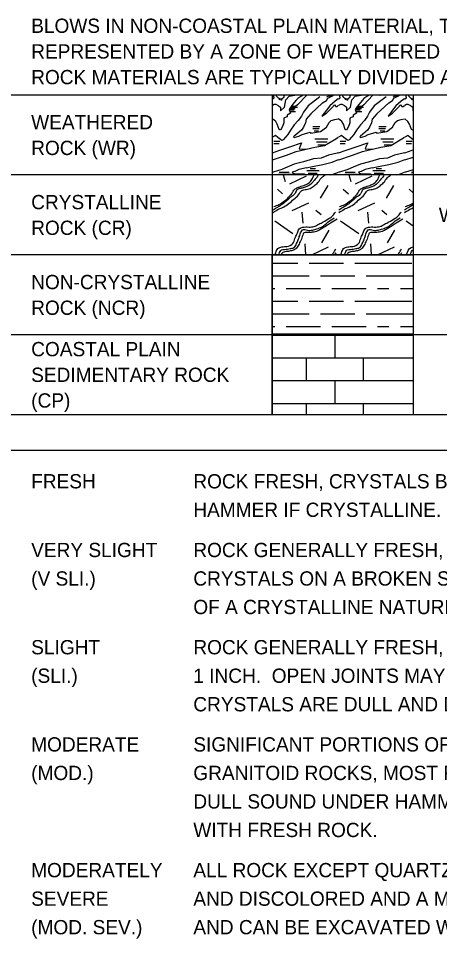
# Model space of a CAD drawing. Extents: x 265553 to 275568, y 168312 to 173522.
# Drawn here: x 267674.3 to 267802.5, y 170735.6 to 171015.3 of the extents above; entities that cross this region are included whole.
import ezdxf

# ---------------------------------------------------------------- set-up
doc = ezdxf.new("R2010")
doc.units = 0
doc.layers.add('Geotech Sheets and Borders Cell', color=7, linetype='Continuous')

msp = doc.modelspace()

# ---------------------------------------------------------------- linework, layer by layer
at = {"layer": 'Geotech Sheets and Borders Cell'}
for p, q in [((268066.96, 170992), (267670.42, 170992)), ((267751.59, 170992), (267751.59, 170894.83)), ((267757.4, 170991.93), (267757.43, 170992)), ((267760.6, 170991.93), (267760.68, 170992)), ((267764.2, 170991.93), (267764.29, 170992)), ((267777.52, 170991.93), (267777.55, 170992)), ((267780.72, 170991.93), (267780.8, 170992)), ((267784.32, 170991.93), (267784.41, 170992)), ((267794.45, 170992), (267794.45, 170894.83)), ((267756.74, 170987.47), (267758.22, 170987.47)), ((267756.87, 170987.91), (267758.59, 170987.91)), ((267757.12, 170988.29), (267759.26, 170988.29)), ((267776.86, 170987.47), (267778.34, 170987.47)), ((267776.99, 170987.91), (267778.71, 170987.91)), ((267777.24, 170988.29), (267779.38, 170988.29)), ((267756.88, 170986.98), (267758.68, 170986.98)), ((267777, 170986.98), (267778.8, 170986.98)), ((267763.88, 170982.48), (267766.08, 170982.48)), ((267763.88, 170981.81), (267765.88, 170981.81)), ((267784, 170982.48), (267786.2, 170982.48)), ((267784, 170981.81), (267786, 170981.81)), ((267764.28, 170981.13), (267765.68, 170981.13)), ((267784.4, 170981.13), (267785.8, 170981.13)), ((267752.08, 170977.98), (267753.88, 170977.98)), ((267752.08, 170977.31), (267753.68, 170977.31)), ((267764.48, 170978.66), (267768.48, 170978.66)), ((267765.08, 170977.76), (267768.28, 170977.76)), ((267765.48, 170976.86), (267767.68, 170976.86)), ((267772.2, 170977.98), (267774, 170977.98)), ((267772.2, 170977.31), (267773.8, 170977.31)), ((267784.6, 170978.66), (267788.6, 170978.66)), ((267785.2, 170977.76), (267788.4, 170977.76)), ((267785.6, 170976.86), (267787.8, 170976.86)), ((267792.32, 170977.98), (267794.12, 170977.98)), ((267792.32, 170977.31), (267793.92, 170977.31)), ((267753.49, 170967.92), (267757.43, 170967.92)), ((267753.68, 170968.53), (267756.68, 170968.53)), ((267762.08, 170969.07), (267765.83, 170969.07)), ((267762.48, 170968.31), (267765.28, 170968.31)), ((267763.08, 170969.66), (267764.68, 170969.66)), ((267773.61, 170967.92), (267777.55, 170967.92)), ((267773.8, 170968.53), (267776.8, 170968.53)), ((267782.2, 170969.07), (267785.95, 170969.07)), ((267782.6, 170968.31), (267785.4, 170968.31)), ((267783.2, 170969.66), (267784.8, 170969.66)), ((267793.73, 170967.92), (267794.45, 170967.92)), ((267793.92, 170968.53), (267794.45, 170968.53)), ((268066.96, 170967.71), (267670.42, 170967.71)), ((267794.45, 170958.67), (267793.41, 170958.02)), ((268066.96, 170943.42), (267670.42, 170943.42)), ((267770.89, 170944.06), (267770.55, 170943.46)), ((267790.89, 170944.06), (267790.55, 170943.46)), ((267794.45, 170943.74), (267794.29, 170943.46)), ((267751.55, 170940.9), (267752.41, 170940.9)), ((267752.41, 170940.9), (267759.35, 170940.9)), ((267762.82, 170940.9), (267773.24, 170940.9)), ((267776.71, 170940.9), (267787.12, 170940.9)), ((267787.12, 170940.9), (267794.06, 170940.9)), ((267751.55, 170937.08), (267752.41, 170937.08)), ((267752.41, 170937.08), (267762.82, 170937.08)), ((267766.29, 170937.08), (267776.71, 170937.08)), ((267780.18, 170937.08), (267787.12, 170937.08)), ((267787.12, 170937.08), (267794.4, 170937.08)), ((267751.55, 170933.22), (267752.37, 170933.22)), ((267755.84, 170933.22), (267766.25, 170933.22)), ((267769.72, 170933.22), (267780.13, 170933.22)), ((267783.6, 170933.22), (267787.07, 170933.22)), ((267790.54, 170933.22), (267794.4, 170933.22)), ((267751.55, 170929.36), (267752.41, 170929.36)), ((267752.41, 170929.36), (267759.35, 170929.36)), ((267762.82, 170929.36), (267773.24, 170929.36)), ((267776.71, 170929.36), (267787.12, 170929.36)), ((267787.12, 170929.36), (267794.06, 170929.36)), ((267751.55, 170925.5), (267752.41, 170925.5)), ((267752.41, 170925.5), (267762.82, 170925.5)), ((267766.29, 170925.5), (267776.71, 170925.5)), ((267780.18, 170925.5), (267787.12, 170925.5)), ((267787.12, 170925.5), (267794.4, 170925.5)), ((267751.55, 170921.64), (267752.37, 170921.64)), ((267755.84, 170921.64), (267766.25, 170921.64)), ((267769.72, 170921.64), (267780.13, 170921.64)), ((267783.6, 170921.64), (267787.07, 170921.64)), ((267790.54, 170921.64), (267794.4, 170921.64)), ((268066.96, 170919.12), (267670.42, 170919.12)), ((267770.68, 170912.14), (267770.68, 170918.99)), ((267751.59, 170912.14), (267794.45, 170912.14)), ((267762, 170905.2), (267762, 170912.14)), ((267779.35, 170905.2), (267779.35, 170912.14)), ((267751.59, 170905.2), (267794.45, 170905.2)), ((267770.68, 170898.26), (267770.68, 170905.2)), ((267751.59, 170898.26), (267794.45, 170898.26)), ((267762, 170894.83), (267762, 170898.26)), ((267779.35, 170894.83), (267779.35, 170898.26)), ((268066.96, 170894.83), (267670.42, 170894.83)), ((268066.96, 170883.98), (267670.42, 170883.98))]:
    msp.add_line(p, q, dxfattribs=at)
for points in [[(267751.64, 170990.85), (267752.14, 170991.13), (267752.05, 170991.72), (267751.95, 170992)], [(267762.08, 170991.93), (267759.28, 170989.01), (267758.68, 170988.56), (267757.28, 170988.56), (267756.68, 170987.66), (267756.88, 170986.98), (267757.08, 170986.53), (267756.08, 170985.86), (267756.08, 170985.41), (267756.08, 170985.41), (267755.48, 170985.18), (267755.08, 170984.96), (267755.08, 170983.61), (267754.68, 170982.48), (267754.08, 170981.36), (267753.68, 170981.58), (267753.08, 170983.16), (267752.62, 170984.01)], [(267753.28, 170991.26), (267752.88, 170991.71), (267752.88, 170992)], [(267753.28, 170991.26), (267753.48, 170991.03), (267753.88, 170990.58), (267754.08, 170991.03), (267754.28, 170990.58), (267754.48, 170990.58), (267754.68, 170991.03), (267755.08, 170991.26), (267755.28, 170991.93)], [(267766.08, 170991.48), (267762.48, 170988.78), (267761.08, 170986.76), (267760.48, 170985.63), (267759.48, 170984.28), (267758.28, 170982.93), (267757.08, 170981.36), (267756.28, 170980.01), (267754.88, 170978.43), (267754.48, 170978.21), (267753.28, 170979.11)], [(267753.51, 170988.73), (267754.08, 170988.33), (267754.08, 170987.21), (267755.28, 170988.33), (267755.68, 170990.58), (267756.68, 170991.71), (267758.48, 170991.93)], [(267760.91, 170992), (267760.63, 170991.74), (267760.25, 170991.55), (267759.35, 170990.98), (267758.76, 170990.37), (267757.85, 170989.27), (267757.28, 170988.56)], [(267771.64, 170990.85), (267770.68, 170990.13), (267769.08, 170988.78), (267768.08, 170987.43), (267766.68, 170985.63), (267768.08, 170986.53), (267769.68, 170988.11), (267770.48, 170989.01), (267770.88, 170988.56), (267771.28, 170988.56), (267771.64, 170988.88)], [(267766.88, 170989.68), (267768.08, 170990.36), (267768.48, 170991.03), (267769.68, 170991.71), (267770.08, 170991.93)], [(267768.2, 170991.48), (267768.58, 170991.63), (267769.14, 170991.75), (267769.83, 170991.97), (267769.87, 170992)], [(267771.76, 170990.85), (267772.26, 170991.13), (267772.17, 170991.72), (267772.07, 170992)], [(267772.2, 170991.93), (267772.34, 170992)], [(267782.2, 170991.93), (267779.4, 170989.01), (267778.8, 170988.56), (267777.4, 170988.56), (267776.8, 170987.66), (267777, 170986.98), (267777.2, 170986.53), (267776.2, 170985.86), (267776.2, 170985.41), (267776.2, 170985.41), (267775.6, 170985.18), (267775.2, 170984.96), (267775.2, 170983.61), (267774.8, 170982.48), (267774.2, 170981.36), (267773.8, 170981.58), (267773.2, 170983.16), (267772.74, 170984.01)], [(267773.4, 170991.26), (267773, 170991.71), (267773, 170992)], [(267773.4, 170991.26), (267773.6, 170991.03), (267774, 170990.58), (267774.2, 170991.03), (267774.4, 170990.58), (267774.6, 170990.58), (267774.8, 170991.03), (267775.2, 170991.26), (267775.4, 170991.93)], [(267786.2, 170991.48), (267782.6, 170988.78), (267781.2, 170986.76), (267780.6, 170985.63), (267779.6, 170984.28), (267778.4, 170982.93), (267777.2, 170981.36), (267776.4, 170980.01), (267775, 170978.43), (267774.6, 170978.21), (267773.4, 170979.11)], [(267773.63, 170988.73), (267774.2, 170988.33), (267774.2, 170987.21), (267775.4, 170988.33), (267775.8, 170990.58), (267776.8, 170991.71), (267778.6, 170991.93)], [(267781.03, 170992), (267780.75, 170991.74), (267780.37, 170991.55), (267779.47, 170990.98), (267778.88, 170990.37), (267777.97, 170989.27), (267777.4, 170988.56)], [(267791.76, 170990.85), (267790.8, 170990.13), (267789.2, 170988.78), (267788.2, 170987.43), (267786.8, 170985.63), (267788.2, 170986.53), (267789.8, 170988.11), (267790.6, 170989.01), (267791, 170988.56), (267791.4, 170988.56), (267791.76, 170988.88)], [(267787, 170989.68), (267788.2, 170990.36), (267788.6, 170991.03), (267789.8, 170991.71), (267790.2, 170991.93)], [(267788.32, 170991.48), (267788.7, 170991.63), (267789.26, 170991.75), (267789.95, 170991.97), (267789.99, 170992)], [(267791.88, 170990.85), (267792.38, 170991.13), (267792.29, 170991.72), (267792.19, 170992)], [(267792.32, 170991.93), (267792.46, 170992)], [(267793.52, 170991.26), (267793.12, 170991.71), (267793.12, 170992)], [(267793.52, 170991.26), (267793.72, 170991.03), (267794.12, 170990.58), (267794.32, 170991.03), (267794.45, 170990.73)], [(267753.51, 170988.73), (267752.73, 170989.12), (267752.19, 170989.12), (267751.64, 170988.88)], [(267766.88, 170989.68), (267763.28, 170986.31), (267761.88, 170984.73), (267761.68, 170983.61), (267761.08, 170982.26), (267760.48, 170981.36), (267758.28, 170979.56), (267758.08, 170979.33), (267758.28, 170979.11), (267759.68, 170979.56), (267760.68, 170980.01), (267763.08, 170980.68), (267763.28, 170980.46), (267766.28, 170980.91), (267768.08, 170982.26), (267768.86, 170983.66)], [(267773.63, 170988.73), (267772.85, 170989.12), (267772.31, 170989.12), (267771.76, 170988.88)], [(267787, 170989.68), (267783.4, 170986.31), (267782, 170984.73), (267781.8, 170983.61), (267781.2, 170982.26), (267780.6, 170981.36), (267778.4, 170979.56), (267778.2, 170979.33), (267778.4, 170979.11), (267779.8, 170979.56), (267780.8, 170980.01), (267783.2, 170980.68), (267783.4, 170980.46), (267786.4, 170980.91), (267788.2, 170982.26), (267788.98, 170983.66)], [(267793.75, 170988.73), (267792.97, 170989.12), (267792.43, 170989.12), (267791.88, 170988.88)], [(267793.75, 170988.73), (267794.32, 170988.33), (267794.32, 170987.21), (267794.45, 170987.33)], [(267752.62, 170984.01), (267751.63, 170984.81)], [(267768.86, 170983.66), (267769.52, 170984.32), (267770.65, 170984.62), (267771.63, 170984.81)], [(267772.74, 170984.01), (267771.75, 170984.81)], [(267788.98, 170983.66), (267789.64, 170984.32), (267790.77, 170984.62), (267791.75, 170984.81)], [(267792.86, 170984.01), (267791.87, 170984.81)], [(267794.45, 170981.6), (267794.32, 170981.36), (267793.92, 170981.58), (267793.32, 170983.16), (267792.86, 170984.01)], [(267753.28, 170979.11), (267752.54, 170979.67), (267751.64, 170979.21)], [(267751.68, 170972.36), (267755.88, 170973.71), (267758.88, 170974.83), (267764.48, 170976.18), (267767.48, 170976.63), (267770.88, 170978.66), (267771.64, 170979.21)], [(267773.4, 170979.11), (267772.66, 170979.67), (267771.76, 170979.21)], [(267771.8, 170972.36), (267776, 170973.71), (267779, 170974.83), (267784.6, 170976.18), (267787.6, 170976.63), (267791, 170978.66), (267791.76, 170979.21)], [(267793.52, 170979.11), (267792.78, 170979.67), (267791.88, 170979.21)], [(267794.45, 170978.41), (267793.52, 170979.11)], [(267751.64, 170974.47), (267753.91, 170975.26), (267756.94, 170976.24), (267760.51, 170977.47), (267760.07, 170976.49), (267759.73, 170975.65), (267761.93, 170975.61)], [(267771.76, 170974.47), (267774.03, 170975.26), (267777.06, 170976.24), (267780.63, 170977.47), (267780.19, 170976.49), (267779.85, 170975.65), (267782.05, 170975.61)], [(267771.64, 170974.47), (267771.28, 170974.38), (267768.68, 170973.71), (267766.48, 170972.81), (267764.08, 170972.58), (267761.08, 170971.68), (267758.28, 170971.01), (267756.08, 170970.11), (267754.48, 170969.43), (267751.88, 170968.53), (267751.68, 170968.53)], [(267791.76, 170974.47), (267791.4, 170974.38), (267788.8, 170973.71), (267786.6, 170972.81), (267784.2, 170972.58), (267781.2, 170971.68), (267778.4, 170971.01), (267776.2, 170970.11), (267774.6, 170969.43), (267772, 170968.53), (267771.8, 170968.53)], [(267791.88, 170974.47), (267794.15, 170975.26), (267794.45, 170975.35)], [(267751.59, 170972.38), (267751.63, 170972.4)], [(267761.86, 170969.88), (267763.77, 170970.29), (267766.96, 170970.88), (267769.8, 170971.61), (267771.75, 170972.4)], [(267781.98, 170969.88), (267783.89, 170970.29), (267787.08, 170970.88), (267789.92, 170971.61), (267791.87, 170972.4)], [(267791.92, 170972.36), (267794.45, 170973.17)], [(267761.86, 170969.88), (267761.08, 170969.66), (267759.68, 170969.43), (267758.48, 170968.76), (267757.68, 170968.53), (267757.88, 170968.31), (267758.88, 170968.08), (267760.68, 170968.08), (267761.28, 170968.08), (267761.44, 170967.71)], [(267769.35, 170967.71), (267770.14, 170967.94), (267771.68, 170968.53)], [(267781.98, 170969.88), (267781.2, 170969.66), (267779.8, 170969.43), (267778.6, 170968.76), (267777.8, 170968.53), (267778, 170968.31), (267779, 170968.08), (267780.8, 170968.08), (267781.4, 170968.08), (267781.56, 170967.71)], [(267789.47, 170967.71), (267790.26, 170967.94), (267791.8, 170968.53)], [(267794.45, 170969.33), (267792.12, 170968.53), (267791.92, 170968.53)], [(267754.86, 170967.71), (267755.49, 170965.74)], [(267756.88, 170965.07), (267761.96, 170967.43)], [(267774.86, 170967.71), (267775.49, 170965.74)], [(267776.88, 170965.07), (267781.96, 170967.43)], [(267753.18, 170963.39), (267754.74, 170962.03)], [(267768.46, 170964.53), (267766.18, 170960.65)], [(267773.18, 170963.39), (267774.74, 170962.03)], [(267788.46, 170964.53), (267786.18, 170960.65)], [(267793.18, 170963.39), (267794.45, 170962.28)], [(267757.66, 170956.91), (267762.74, 170959.27)], [(267764.88, 170957.06), (267766.44, 170955.7)], [(267777.66, 170956.91), (267782.74, 170959.27)], [(267784.88, 170957.06), (267786.44, 170955.7)], [(267760.6, 170956.39), (267760.84, 170953.07)], [(267780.6, 170956.39), (267780.84, 170953.07)], [(267752.31, 170953.74), (267757.87, 170949.9)], [(267768.8, 170950.99), (267766.52, 170947.11)], [(267772.31, 170953.74), (267777.87, 170949.9)], [(267788.8, 170950.99), (267786.52, 170947.11)], [(267792.31, 170953.74), (267794.45, 170952.26)], [(267761.47, 170946.76), (267761.71, 170943.46)], [(267763.64, 170943.47), (267768.72, 170945.83)], [(267781.47, 170946.76), (267781.71, 170943.46)], [(267783.64, 170943.47), (267788.72, 170945.83)]]:
    msp.add_lwpolyline(points, dxfattribs=at)
for points in [[(267751.55, 170943.46), (267794.4, 170943.46), (267794.4, 170919.3), (267751.55, 170919.3)], [(267751.59, 170918.99), (267794.45, 170918.99), (267794.45, 170894.83), (267751.59, 170894.83)]]:
    msp.add_lwpolyline(points, close=True, dxfattribs=at)
for points in [[(267752.01, 170958.18), (267753.61, 170958.7), (267755.29, 170959.86), (267756.53, 170960.94), (267756.77, 170961.3), (267757.57, 170962.14), (267758.09, 170963.06), (267759.09, 170963.78), (267760.01, 170964.14), (267761.61, 170964.7), (267762.57, 170965.18), (267763.65, 170966.38), (267764.13, 170967.38), (267764.35, 170967.71)], [(267765.52, 170967.71), (267765.21, 170967.1), (267764.41, 170966.18), (267763.69, 170965.3), (267762.57, 170964.46), (267761.57, 170964.02), (267760.37, 170963.66), (267759.69, 170963.5), (267758.93, 170963.02), (267758.69, 170962.54), (267758.25, 170961.78), (267757.01, 170960.86), (267756.17, 170960.1), (267755.41, 170959.42), (267754.49, 170958.7), (267753.41, 170958.02)], [(267754.97, 170957.94), (267756.65, 170959.02), (267758.13, 170960.38), (267759.53, 170961.66), (267760.53, 170962.98), (267761.93, 170963.3), (267763.45, 170963.78), (267764.65, 170964.7), (267765.69, 170965.66), (267766.17, 170966.42)], [(267766.17, 170966.42), (267767.13, 170967.34), (267767.68, 170967.71)], [(267772.01, 170958.18), (267773.61, 170958.7), (267775.29, 170959.86), (267776.53, 170960.94), (267776.77, 170961.3), (267777.57, 170962.14), (267778.09, 170963.06), (267779.09, 170963.78), (267780.01, 170964.14), (267781.61, 170964.7), (267782.57, 170965.18), (267783.65, 170966.38), (267784.13, 170967.38), (267784.35, 170967.71)], [(267785.52, 170967.71), (267785.21, 170967.1), (267784.41, 170966.18), (267783.69, 170965.3), (267782.57, 170964.46), (267781.57, 170964.02), (267780.37, 170963.66), (267779.69, 170963.5), (267778.93, 170963.02), (267778.69, 170962.54), (267778.25, 170961.78), (267777.01, 170960.86), (267776.17, 170960.1), (267775.41, 170959.42), (267774.49, 170958.7), (267773.41, 170958.02)], [(267774.97, 170957.94), (267776.65, 170959.02), (267778.13, 170960.38), (267779.53, 170961.66), (267780.53, 170962.98), (267781.93, 170963.3), (267783.45, 170963.78), (267784.65, 170964.7), (267785.69, 170965.66), (267786.17, 170966.42)], [(267786.17, 170966.42), (267787.13, 170967.34), (267787.68, 170967.71)], [(267753.41, 170958.02), (267752.41, 170957.42), (267751.81, 170956.98)], [(267754.97, 170957.94), (267753.41, 170957.18), (267751.81, 170956.22)], [(267773.41, 170958.02), (267772.41, 170957.42), (267771.81, 170956.98)], [(267774.97, 170957.94), (267773.41, 170957.18), (267771.81, 170956.22)], [(267793.41, 170958.02), (267792.41, 170957.42), (267791.81, 170956.98)], [(267794.45, 170957.7), (267793.41, 170957.18), (267791.81, 170956.22)], [(267792.01, 170958.18), (267793.61, 170958.7), (267794.45, 170959.23)], [(267759.09, 170949.74), (267759.21, 170950.1), (267759.81, 170951.34), (267760.81, 170951.82), (267762.69, 170951.9), (267764.29, 170952.06), (267765.73, 170952.74), (267767.09, 170953.46), (267768.93, 170954.54)], [(267760.09, 170949.74), (267760.09, 170949.86), (267760.33, 170950.42), (267760.77, 170951.06), (267762.25, 170950.94), (267763.81, 170950.98), (267765.17, 170951.34), (267766.73, 170951.94), (267768.53, 170953.38), (267770.45, 170954.7)], [(267771.32, 170954.27), (267769.32, 170953.07), (267768.08, 170952.23), (267766.72, 170951.43), (267765.4, 170950.71), (267763.76, 170950.31), (267762.28, 170950.19), (267761.56, 170950.19), (267761.08, 170950.07), (267760.88, 170949.47)], [(267768.93, 170954.54), (267769.93, 170955.34), (267770.77, 170956.46)], [(267779.09, 170949.74), (267779.21, 170950.1), (267779.81, 170951.34), (267780.81, 170951.82), (267782.69, 170951.9), (267784.29, 170952.06), (267785.73, 170952.74), (267787.09, 170953.46), (267788.93, 170954.54)], [(267780.09, 170949.74), (267780.09, 170949.86), (267780.33, 170950.42), (267780.77, 170951.06), (267782.25, 170950.94), (267783.81, 170950.98), (267785.17, 170951.34), (267786.73, 170951.94), (267788.53, 170953.38), (267790.45, 170954.7)], [(267791.32, 170954.27), (267789.32, 170953.07), (267788.08, 170952.23), (267786.72, 170951.43), (267785.4, 170950.71), (267783.76, 170950.31), (267782.28, 170950.19), (267781.56, 170950.19), (267781.08, 170950.07), (267780.88, 170949.47)], [(267788.93, 170954.54), (267789.93, 170955.34), (267790.77, 170956.46)], [(267752.4, 170943.46), (267752.65, 170944.06), (267753.29, 170945.34), (267754.53, 170945.86), (267756.05, 170946.02), (267757.85, 170946.86), (267758.49, 170948.42), (267759.09, 170949.74)], [(267753.42, 170943.46), (267753.65, 170943.78), (267754.41, 170944.98), (267755.33, 170945.1), (267757.01, 170945.34), (267758.13, 170945.62), (267758.97, 170946.86), (267759.49, 170948.02), (267759.81, 170948.98), (267760.09, 170949.74)], [(267760.89, 170949.49), (267760.85, 170949.45), (267760.57, 170948.61), (267759.89, 170947.05), (267759.13, 170945.73), (267758.29, 170944.97), (267757.17, 170944.61), (267755.77, 170944.41), (267755.13, 170944.29), (267754.57, 170943.93), (267754.29, 170943.46)], [(267772.4, 170943.46), (267772.65, 170944.06), (267773.29, 170945.34), (267774.53, 170945.86), (267776.05, 170946.02), (267777.85, 170946.86), (267778.49, 170948.42), (267779.09, 170949.74)], [(267773.42, 170943.46), (267773.65, 170943.78), (267774.41, 170944.98), (267775.33, 170945.1), (267777.01, 170945.34), (267778.13, 170945.62), (267778.97, 170946.86), (267779.49, 170948.02), (267779.81, 170948.98), (267780.09, 170949.74)], [(267780.89, 170949.49), (267780.85, 170949.45), (267780.57, 170948.61), (267779.89, 170947.05), (267779.13, 170945.73), (267778.29, 170944.97), (267777.17, 170944.61), (267775.77, 170944.41), (267775.13, 170944.29), (267774.57, 170943.93), (267774.29, 170943.46)], [(267792.4, 170943.46), (267792.65, 170944.06), (267793.29, 170945.34), (267794.45, 170945.84)], [(267769.81, 170943.46), (267770.05, 170943.82), (267770.93, 170945.22)], [(267789.81, 170943.46), (267790.05, 170943.82), (267790.93, 170945.22)], [(267793.42, 170943.46), (267793.65, 170943.78), (267794.41, 170944.98), (267794.45, 170944.99)]]:
    msp.add_spline(points, degree=3, dxfattribs=at)

# ---------------------------------------------------------------- texts
for s, height, p in [('BLOWS IN NON-COASTAL PLAIN MATERIAL, THE TRANSITION BETWEEN SOIL AND ROCK IS OFTEN', 4.3381, (267678.23, 171010.91)), ('REPRESENTED BY A ZONE OF WEATHERED ROCK.', 4.3381, (267678.23, 171003.11)), ('ROCK MATERIALS ARE TYPICALLY DIVIDED AS FOLLOWS:', 4.3381, (267678.23, 170995.3)), ('WEATHERED', 4.338, (267678.23, 170981.59)), ('ROCK (WR)', 4.338, (267678.23, 170973.78)), ('CRYSTALLINE', 4.3381, (267678.23, 170957.3)), ('WOULD YIELD SPT REFUSAL IF TESTED.  ROCK TYPE INCLUDES GRANITE, ', 4.3381, (267802.26, 170953.4)), ('ROCK (CR)', 4.338, (267678.23, 170949.49)), ('NON-CRYSTALLINE', 4.3381, (267678.23, 170933)), ('ROCK (NCR)', 4.338, (267678.23, 170925.19)), ('COASTAL PLAIN', 4.3381, (267678.23, 170912.61)), ('SEDIMENTARY ROCK', 4.3381, (267678.23, 170904.81)), ('(CP)', 4.338, (267678.23, 170897)), ('FRESH', 4.338, (267678.23, 170872.44)), ('ROCK FRESH, CRYSTALS BRIGHT, FEW JOINTS MAY SHOW SLIGHT STAINING.  ROCK RINGS UNDER ', 4.3381, (267727.56, 170872.44)), ('HAMMER IF CRYSTALLINE.', 4.3381, (267727.56, 170863.77)), ('VERY SLIGHT ', 4.3381, (267678.23, 170851.55)), ('ROCK GENERALLY FRESH, JOINTS STAINED, SOME JOINTS MAY SHOW THIN CLAY COATINGS IF OPEN, ', 4.3381, (267727.56, 170851.55)), ('(V SLI.)', 4.338, (267678.23, 170842.89)), ('CRYSTALS ON A BROKEN SPECIMEN FACE SHINE BRIGHTLY.  ROCK RINGS UNDER HAMMER BLOWS IF ', 4.3381, (267727.56, 170842.89)), ('OF A CRYSTALLINE NATURE.', 4.3381, (267727.56, 170834.22)), ('SLIGHT', 4.338, (267678.23, 170822)), ('ROCK GENERALLY FRESH, JOINTS STAINED AND DISCOLORATION EXTENDS INTO ROCK UP TO ', 4.3381, (267727.56, 170822)), ('(SLI.)', 4.338, (267678.23, 170813.33)), ('1 INCH.  OPEN JOINTS MAY CONTAIN CLAY.  IN GRANITOID ROCKS SOME OCCASIONAL FELDSPAR ', 4.3381, (267727.56, 170813.33)), ('CRYSTALS ARE DULL AND DISCOLORED.  CRYSTALLINE ROCKS RING UNDER HAMMER BLOWS.', 4.3381, (267727.56, 170804.66)), ('MODERATE', 4.338, (267678.23, 170792.45)), ('SIGNIFICANT PORTIONS OF ROCK SHOW DISCOLORATION AND WEATHERING EFFECTS.  IN ', 4.3381, (267727.56, 170792.45)), ('(MOD.)', 4.338, (267678.23, 170783.78)), ('GRANITOID ROCKS, MOST FELDSPARS ARE DULL AND DISCOLORED, SOME SHOW CLAY.  ROCK HAS ', 4.3381, (267727.56, 170783.78)), ('DULL SOUND UNDER HAMMER BLOWS AND SHOWS SIGNIFICANT LOSS OF STRENGTH AS COMPARED ', 4.3381, (267727.56, 170775.11)), ('WITH FRESH ROCK.', 4.3381, (267727.56, 170766.44)), ('MODERATELY', 4.338, (267678.23, 170754.23)), ('ALL ROCK EXCEPT QUARTZ DISCOLORED OR STAINED.  IN GRANITOID ROCKS, ALL FELDSPARS DULL ', 4.3381, (267727.56, 170754.23)), ('SEVERE', 4.338, (267678.23, 170745.56)), ('AND DISCOLORED AND A MAJORITY SHOW KAOLINIZATION.  ROCK SHOWS SEVERE LOSS OF STRENGTH', 4.3381, (267727.56, 170745.56)), ('(MOD. SEV.)', 4.3381, (267678.23, 170736.89)), ('AND CAN BE EXCAVATED WITH A GEOLOGIST\'S PICK.  ROCK GIVES "CLUNK" SOUND WHEN STRUCK.', 4.3381, (267727.56, 170736.89))]:
    msp.add_text(s, height=height, dxfattribs=at).set_placement(p)

doc.saveas('drawing.dxf')
